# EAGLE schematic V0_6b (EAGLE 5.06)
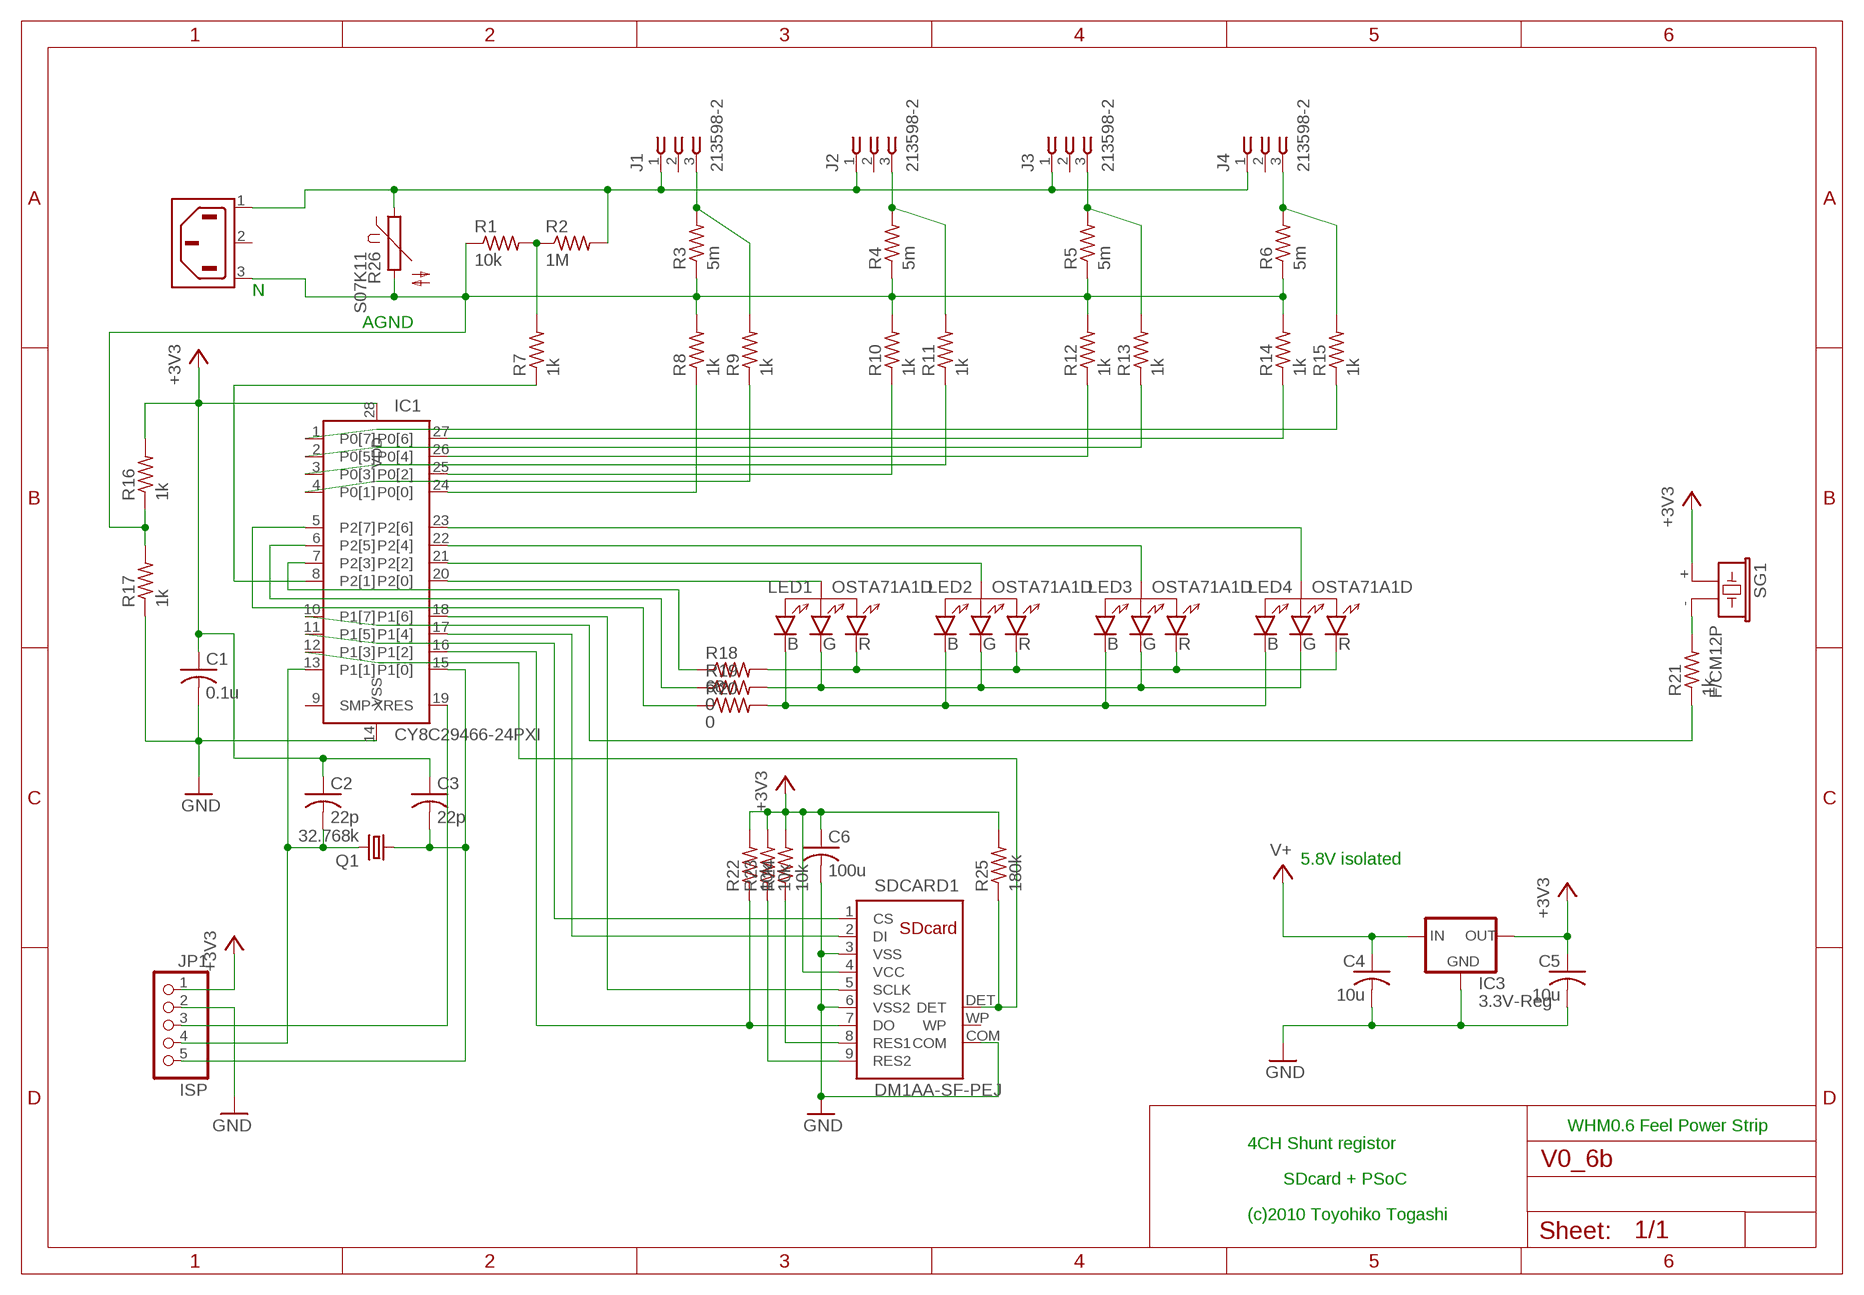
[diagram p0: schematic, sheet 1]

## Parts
C1  0.1u  C-USC0603  [C0603]
C2  22p  C-USC0603  [C0603]
C3  22p  C-USC0603  [C0603]
C4  10u  C-USC0603  [C0603]
C5  10u  C-USC0603  [C0603]
C6  100u  C-USC0603  [C0603]
IC1  CY8C29466-24PXI  [DIL28-3]
IC3  3.3V-Reg  XC63FPM  [SOT23]
J1  213598-2  [213598-2]
J2  213598-2  [213598-2]
J3  213598-2  [213598-2]
J4  213598-2  [213598-2]
JP1  ISP  PINHD-1X5  [1X05]
LED1  OSTA71A1D  [FLUX-LED]
LED2  OSTA71A1D  [FLUX-LED]
LED3  OSTA71A1D  [FLUX-LED]
LED4  OSTA71A1D  [FLUX-LED]
Q1  32.768k  CRYSTALHC49UP  [HC49UP]
R1  10k  R-US_R0603  [R0603]
R2  1M  R-US_R0603  [R0603]
R3  5m  R-US_R3225  [R3225]
R4  5m  R-US_R3225  [R3225]
R5  5m  R-US_R3225  [R3225]
R6  5m  R-US_R3225  [R3225]
R7  1k  R-US_R0603  [R0603]
R8  1k  R-US_R0603  [R0603]
R9  1k  R-US_R0603  [R0603]
R10  1k  R-US_R0603  [R0603]
R11  1k  R-US_R0603  [R0603]
R12  1k  R-US_R0603  [R0603]
R13  1k  R-US_R0603  [R0603]
R14  1k  R-US_R0603  [R0603]
R15  1k  R-US_R0603  [R0603]
R16  1k  R-US_R0603  [R0603]
R17  1k  R-US_R0603  [R0603]
R18  68  R-US_R0603  [R0603]
R19  0  R-US_R0603  [R0603]
R20  0  R-US_R0603  [R0603]
R21  1k  R-US_R0603  [R0603]
R22  10k  R-US_R0603  [R0603]
R23  10k  R-US_R0603  [R0603]
R24  10k  R-US_R0603  [R0603]
R25  180k  R-US_R0603  [R0603]
R26  S07K11  [S07K11]
SDCARD1  DM1AA-SF-PEJ  [DM1AA]
SG1  F/CM12P  [F/CM12P]
X1  6ESRM-P  [6ESRM-P]

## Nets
+3V3: C1.1 C2.1 C3.1 C5.1 C6.1 IC1.28(VDD) IC3.2(OUT) JP1.1 R16.2 R22.2 R23.2 R24.2 R25.2 SDCARD1.4(VCC) SG1.+
GND: C1.2 C4.2 C5.2 C6.2 IC1.14(VSS) IC3.1(GND) JP1.2 R17.1 SDCARD1.3(VSS) SDCARD1.6(VSS2) SDCARD1.COM
N$1: C2.2 IC1.13(P1[1]) JP1.4 Q1.2
N$2: IC1.8(P2[1]) R7.1
N$3: IC1.24(P0[0]) R8.1
N$4: IC1.4(P0[1]) R9.1
N$5: C3.2 IC1.15(P1[0]) JP1.5 Q1.1
N$6: IC1.25(P0[2]) R10.1
N$7: IC1.20(P2[0]) LED1.P$1
N$8: IC1.21(P2[2]) LED2.P$1
N$9: IC1.22(P2[4]) LED3.P$1
N$10: IC1.10(P1[7]) R21.1
N$11: IC1.23(P2[6]) LED4.P$1
N$12: IC1.3(P0[3]) R11.1
N$13: IC1.26(P0[4]) R12.1
N$14: IC1.2(P0[5]) R13.1
N$15: IC1.7(P2[3]) R18.1
N$16: LED1.P$3 LED2.P$3 LED3.P$3 LED4.P$3 R19.2
N$17: IC1.17(P1[4]) SDCARD1.2(DI)
N$18: LED1.P$2 LED2.P$2 LED3.P$2 LED4.P$2 R20.2
N$19: IC1.6(P2[5]) R19.1
N$20: IC1.12(P1[3]) R25.1 SDCARD1.DET
N$22: IC1.19(XRES) JP1.3
N$23: IC1.5(P2[7]) R20.1
N$24: R1.2 R2.1 R7.2
N$25: J1.3 R3.2 R9.2
N$26: R21.2 SG1.-
N$27: J2.3 R4.2 R11.2
N$28: LED1.P$4 LED2.P$4 LED3.P$4 LED4.P$4 R18.2
N$29: J3.3 R5.2 R13.2
N$30: J4.3 R6.2 R15.2
N$31: IC1.27(P0[6]) R14.1
N$32: IC1.18(P1[6]) SDCARD1.5(SCLK)
N$33: IC1.16(P1[2]) R22.1 SDCARD1.7(DO)
N$34: IC1.1(P0[7]) R15.1
N$36: R1.1 R3.1 R4.1 R5.1 R6.1 R8.2 R10.2 R12.2 R14.2 R16.1 R17.2 R26.2 X1.3(AC2)
N$39: IC1.11(P1[5]) SDCARD1.1(CS)
N$40: J1.1 J2.1 J3.1 J4.1 R2.2 R26.1 X1.1(AC1)
N$41: R23.1 SDCARD1.9(RES2)
N$42: R24.1 SDCARD1.8(RES1)
V+: C4.1 IC3.3(IN)
Unconnected: J1.2 J2.2 J3.2 J4.2 SDCARD1.WP X1.2(SH)

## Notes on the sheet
- N
- AGND
- 5.8V isolated
- WHM0.6 Feel Power Strip
- 4CH Shunt registor
- SDcard + PSoC
- (c)2010 Toyohiko Togashi

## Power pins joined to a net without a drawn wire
SMP: IC1.9(SMP)

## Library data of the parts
C1-C6 = rcl:C-US: CAPACITOR, American symbol
IC1 = TOG:CY8C29466*: Cypress PSoC Mixe-Signal Array Flash32K,RAM2K, Digital block 16, Analog block 12
IC3 = v-reg:XC63FP: Positiv Voltage Regulators www.torex.co.jp/english/product/pro02/pdf/0201_xc62fp.pdf
J1-J4 = con-amp:213598-2: AC Jack Source: ENG_CD_213598_M.pdf
JP1 = pinhead:PINHD-1X5: PIN HEADER
LED1-LED4 = TOG:OSTA71A1D: Super Flux RGB LED
Q1 = crystal:CRYSTAL: CRYSTAL
R1-R25 = rcl:R-US_: RESISTOR, American symbol
R26 = varistor:S07K11: VARISTOR
SDCARD1 = TOG:DM1AA-SF-PEJ: SDcard connector HIROSE
SG1 = buzzer:F/CM12P: BUZZER
X1 = con-tycoelectronics:6ESRM-P: AC Connector 120/250 VAC Source: http://catalog.tycoelectronics.com .. ENG_DS_1654001_1099_SR_0406.pdf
